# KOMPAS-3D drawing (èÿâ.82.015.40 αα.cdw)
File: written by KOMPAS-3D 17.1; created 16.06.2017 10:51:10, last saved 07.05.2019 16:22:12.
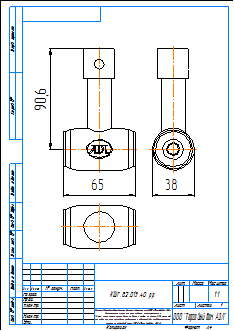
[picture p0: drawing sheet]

Sheet 1: A4, portrait

Title block, sheet 1: name: КШГ.82.015.40 рр; material: Внимание! Данный продукт является объектом авторского права ООО «Торговый Дом АДЛ». / Запрещается изменение, копирование, распространение / (в том числе путем копирования на другие сайты и ресурсы в Интернете) / или любое иное использование информации и объектов без предварительного / согласия правообладателя (ООО «Торговый Дом АДЛ»).; scale: 1:1; sheets: 1; organisation: ООО "Торговый дом АДЛ"; sheet format: A4; stored path: C:\Users\tra\Desktop\2д чертежи\Шаровые краны БИВАЛ\КШ_Бивал_серия_82_85\KOMPAS 2D\КШГ.82.015.40 рр.cdw

Views: Спереди 1, Проекционный вид 2, Проекционный вид 3
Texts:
  Klimkovich
  ADL
Dimensions and other numbers on the sheet: 65; 90,6; 38; 1:1; 1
